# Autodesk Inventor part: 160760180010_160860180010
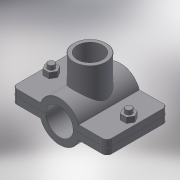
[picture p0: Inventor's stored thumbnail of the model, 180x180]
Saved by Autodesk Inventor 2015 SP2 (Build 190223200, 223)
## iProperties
Created: 2017-05
Part Number: 160760180010_160860180010
Material: Generic
Description: PLASSON SADDLE 180-1"
Document SubType Name: Modeling
Designer: KIM
Density: 1 g/cm^3
Appearance: Default
Author: KIM
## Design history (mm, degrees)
derived "16076.ipt"
feature "Solid1::16076.ipt"
feature "Solid2::16076.ipt"
tag "TaggingFeature1"
body "Solid1"
other parameters: "d0" = 198, "d1" = 245, "d4" = 154, "d5" = 0, "d6" = 12.25, "d7" = 245, "d8" = 0.1, "d10" = 0, "d11" = 1.8, "d14" = 39.3783, "d20" = 1.8, "d23" = 1.8, "d36" = 15, "d37" = 12, "d38" = 98, "d39" = 0, "d40" = 3, "d41" = 5, "d42" = 0, "d44" = 3, "d45" = 0, "d46" = 1.8, "d51" = 122, "d52" = 30.291, "d53" = 21, "d54" = 0, "d55" = 25, "d57" = 0, "d58" = 194.4, "d60" = 0, "d62" = 15, "d63" = 12, "B_" = 25, "G_" = 30.291, "A_" = 122, "L_" = 245, "L_1" = 154, "l_2" = 21
